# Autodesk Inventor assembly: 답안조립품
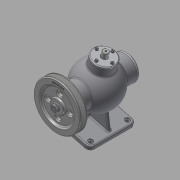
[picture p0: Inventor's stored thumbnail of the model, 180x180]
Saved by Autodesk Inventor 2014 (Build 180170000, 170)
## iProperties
Created: 2015-10
Part Number: 답안조립품
Document SubType Name: Assembly
Designer: youjin11
Author: youjin11
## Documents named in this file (16)
- C:\Users\youjin11\Desktop\451010V1005\답안조립품.iam
- C:\Users\youjin11\Desktop\451010V1005\본체6.ipt
- C:\Users\youjin11\Desktop\451010V1005\앞커버.ipt
- C:\Users\youjin11\Desktop\451010V1005\뒤커버.ipt
- C:\Users\youjin11\Desktop\451010V1005\볼트 M 4 x 12.ipt
- C:\Users\youjin11\Desktop\451010V1005\볼트 M4 x 16.ipt
- C:\Users\youjin11\Desktop\451010V1005\상부커버.ipt
- C:\Users\youjin11\Desktop\451010V1005\베어링- 6202.ipt
- KS B 2023 - 6202 - 15 x 35 x 11 - 7.8.ipt
- C:\Users\youjin11\Desktop\451010V1005\오일실 15 30 7.ipt
- C:\Users\youjin11\Desktop\451010V1005\부시.ipt
- C:\Users\youjin11\Desktop\451010V1005\편심축.ipt
- C:\Users\youjin11\Desktop\451010V1005\슬라이드.ipt
- C:\Users\youjin11\Desktop\451010V1005\키 4 x 4 x 12.ipt
- C:\Users\youjin11\Desktop\451010V1005\V-벨트풀리.ipt
- C:\Users\youjin11\Desktop\451010V1005\너트 M8.ipt
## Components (15 placed, 4 different names)
1. KS B 2023 - 6202 - 15 x 35 x 11 - 7.8:1
2. KS B 2023 - 6202 - 15 x 35 x 11 - 7.8:2
3. V-벨트풀리:1 — 플러쉬:1
4. ISO 4762 M4 x 16:1
5. ISO 4762 M4 x 16:3
6. ISO 4762 M4 x 16:4
7. ISO 4762 M4 x 16:5
8. ISO 4762 M4 x 16:2
9. ISO 4762 M4 x 16:6
10. ISO 4762 M4 x 16:7
11. ISO 4762 M4 x 16:8
12. KS B 1021 - 에 따름 ISO 1207 - 미터 A  M 4 x 12:1
13. KS B 1021 - 에 따름 ISO 1207 - 미터 A  M 4 x 12:2
14. KS B 1021 - 에 따름 ISO 1207 - 미터 A  M 4 x 12:3
15. KS B 1021 - 에 따름 ISO 1207 - 미터 A  M 4 x 12:4
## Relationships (1: Flush 1)
- 플러쉬:1 [Flush]: V-벨트풀리:1
